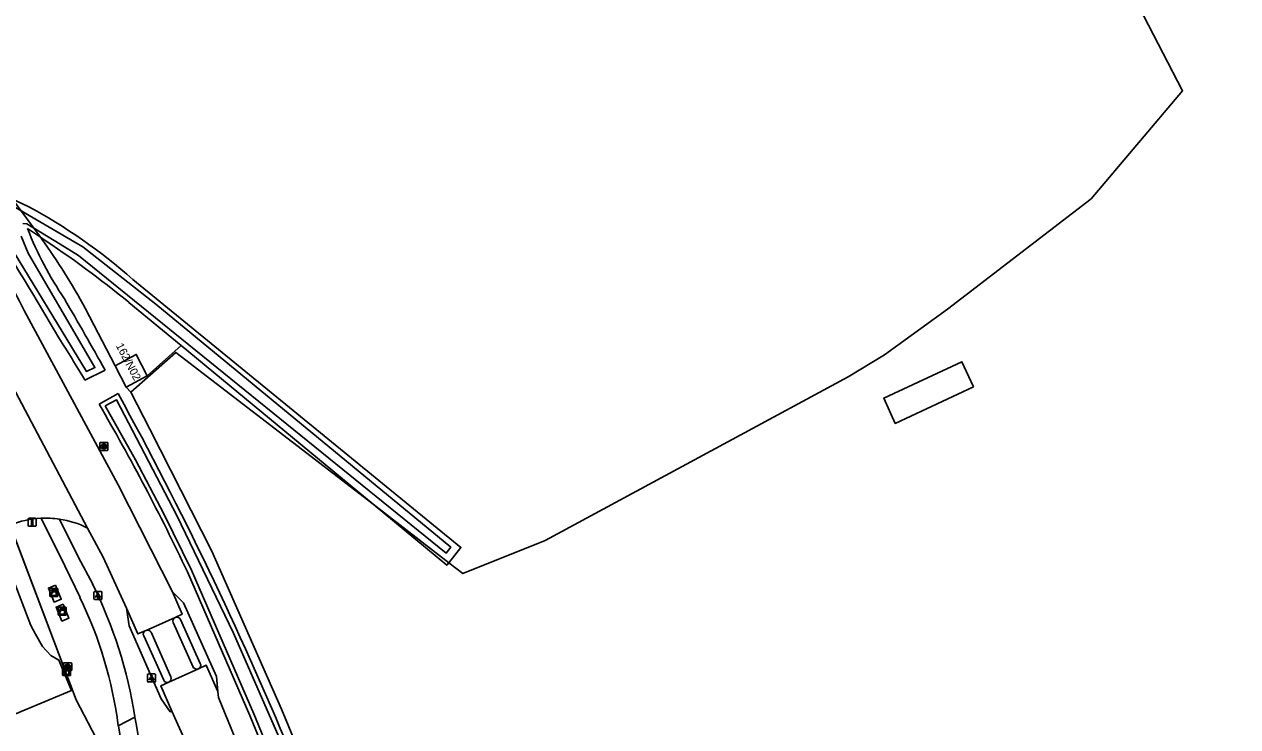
# Model space of a CAD drawing. Extents: x 156061 to 157804, y 383451 to 385640.
# Drawn here: x 157555.9 to 157707.5, y 383885.9 to 383973.7 of the extents above; entities that cross this region are included whole.
import ezdxf

# ---------------------------------------------------------------- set-up
doc = ezdxf.new("R2010")
doc.units = 0
for name, color, linetype in [('IMGEO_Bouwland', 7, 'Continuous'), ('IMGEO_Brandkraan', 7, 'Continuous'), ('IMGEO_Fietspad_gesloten', 7, 'Continuous'), ('IMGEO_Grasland_overig', 7, 'Continuous'), ('IMGEO_Groenvoorziening', 7, 'Continuous'), ('IMGEO_Hek', 7, 'Continuous'), ('IMGEO_Kast', 7, 'Continuous'), ('IMGEO_Lage_trafo', 7, 'Continuous'), ('IMGEO_Lichtpunt', 7, 'Continuous'), ('IMGEO_Muur', 7, 'Continuous'), ('IMGEO_Pand', 7, 'Continuous'), ('IMGEO_Pand_nummerreeks', 7, 'Continuous'), ('IMGEO_Rijbaan_lokaal_gesloten', 7, 'Continuous'), ('IMGEO_Rijbaan_lokaal_open', 7, 'Continuous'), ('IMGEO_Rioolput', 7, 'Continuous'), ('IMGEO_Verkeersbordpaal', 7, 'Continuous'), ('IMGEO_Voetpad_open', 7, 'Continuous'), ('IMGEO_Waterloop', 7, 'Continuous'), ('IMGEO_Woonerf_open', 7, 'Continuous')]:
    doc.layers.add(name, color=color, linetype=linetype)

msp = doc.modelspace()

# ---------------------------------------------------------------- linework, layer by layer
at = {"layer": 'IMGEO_Bouwland'}
for points in [[(157608.98, 383906.43), (157610.74, 383905.07), (157621.02, 383909.21), (157658.89, 383929.67), (157663.41, 383932.41), (157671.29, 383938.14), (157689.24, 383951.93), (157700.65, 383965.44), (157683.71, 383998.2), (157679.87, 383996.94), (157678.86, 384000), (157676.51, 384007.11)], [(157608.98, 383906.43), (157608.72, 383906.11), (157599.51, 383913.73), (157575.52, 383933.59)], [(157702.8, 383849.36), (157707.55, 383840.38), (157700.2, 383834.34), (157695.92, 383830.81), (157693.54, 383829.05), (157691.04, 383827.5), (157689.84, 383826.75), (157683.07, 383823.26), (157676.59, 383820.43), (157634.61, 383803.39), (157626.26, 383803.73), (157620.27, 383810.26), (157611.86, 383828.59), (157592.66, 383877.06), (157588.09, 383888.13), (157579.36, 383907.86), (157571.61, 383923.12), (157569.27, 383927.73), (157568.67, 383928.38)]]:
    msp.add_lwpolyline(points, dxfattribs=at)
at = {"layer": 'IMGEO_Brandkraan'}
for p, q in [((157565.39, 383920.54), (157565.39, 383921.39)), ((157565.46, 383921.46), (157566.32, 383921.46)), ((157565.9, 383920.68), (157565.87, 383920.68)), ((157565.88, 383921.24), (157565.9, 383921.24)), ((157566.39, 383921.39), (157566.39, 383920.54)), ((157566.32, 383920.46), (157565.46, 383920.46))]:
    msp.add_line(p, q, dxfattribs=at)
for points in [[(157565.39, 383920.54), (157565.39, 383921.39)], [(157565.46, 383921.46), (157566.32, 383921.46)], [(157565.74, 383921.16), (157565.74, 383920.76), (157565.95, 383920.76)], [(157565.97, 383921.16), (157565.74, 383921.16)], [(157565.92, 383921.08), (157565.86, 383921.08), (157565.86, 383921)], [(157565.86, 383921), (157565.92, 383921)], [(157565.92, 383920.93), (157565.86, 383920.93), (157565.86, 383920.85)], [(157565.86, 383920.85), (157565.92, 383920.85)], [(157566.39, 383921.39), (157566.39, 383920.54)], [(157566.32, 383920.46), (157565.46, 383920.46)]]:
    msp.add_lwpolyline(points, dxfattribs=at)
for centre, radius, start, end in [((157565.47, 383921.39), 0.0765, 91.552, 178.448), ((157565.47, 383921.39), 0.0765, 91.552, 178.448), ((157565.47, 383920.54), 0.0765, 181.552, 268.448), ((157565.47, 383920.54), 0.0765, 181.552, 268.448), ((157565.92, 383921.04), 0.0379, 267.8285, 90.9355), ((157565.92, 383920.89), 0.0404, 269.8759, 90.5077), ((157565.96, 383921.01), 0.251, 268.6676, 293.5347), ((157565.97, 383921.02), 0.145, 59.4692, 91.5367), ((157566, 383921.06), 0.0922, 285.5137, 58.1501), ((157566, 383920.87), 0.105, 301.3115, 78.989), ((157566.31, 383921.39), 0.0765, 1.552, 88.448), ((157566.31, 383921.39), 0.0765, 1.552, 88.448), ((157566.31, 383920.54), 0.0765, 271.552, 358.448), ((157566.31, 383920.54), 0.0765, 271.552, 358.448)]:
    msp.add_arc(centre, radius, start, end, dxfattribs=at)
for centre, major_axis, ratio, start_param, end_param in [((157565.88, 383920.96), (-0.387, 0.002), 0.722429, 4.712389, 7.853982), ((157565.9, 383920.96), (-0.39, 0.002), 0.717154, 1.570796, 4.712389)]:
    msp.add_ellipse(centre, major_axis=major_axis, ratio=ratio, start_param=start_param, end_param=end_param, dxfattribs=at)
at = {"layer": 'IMGEO_Fietspad_gesloten'}
for points in [[(157558.03, 383912), (157561.01, 383906.05), (157562.9, 383902.08)], [(157564.49, 383903.75), (157562.73, 383907.09), (157560.33, 383911.89)], [(157569.76, 383887.14), (157567.68, 383886.03)]]:
    msp.add_lwpolyline(points, dxfattribs=at)
for centre, radius, start, end in [((157558.61, 383900.32), 11.69, 81.5344, 92.8402), ((157512.71, 383878.19), 57.74, 8.9216, 26.283), ((157515.53, 383879.2), 52.6, 7.4631, 25.7787), ((157650.23, 383900.28), 81.53, 189.2732, 201.2187), ((157649.02, 383899.57), 82.45, 189.4495, 201.0896)]:
    msp.add_arc(centre, radius, start, end, dxfattribs=at)
at = {"layer": 'IMGEO_Grasland_overig'}
for points in [[(157558.11, 383946.93), (157557.98, 383947.12)], [(157575.52, 383933.59), (157569, 383938.98)], [(157567.3, 383931.05), (157563.55, 383938.24)], [(157575.52, 383933.59), (157571.31, 383929.81)], [(157553.25, 383886.86), (157561.82, 383890.46), (157560.26, 383894.25), (157559.24, 383894.85), (157558.2, 383895.95), (157557.34, 383897.5), (157556.74, 383898.58), (157552.12, 383910.57)], [(157554.17, 383911.13), (157562.42, 383889.31), (157565.92, 383882.59)]]:
    msp.add_lwpolyline(points, dxfattribs=at)
for centre, radius, start, end in [((157477.63, 383826.71), 144.76, 50.8627, 56.2846), ((157490.52, 383898.58), 83.1, 28.5032, 35.5798)]:
    msp.add_arc(centre, radius, start, end, dxfattribs=at)
at = {"layer": 'IMGEO_Groenvoorziening'}
for points in [[(157554.47, 383951.89), (157556.32, 383951.02)], [(157557.98, 383947.12), (157556.34, 383948.2)], [(157569.52, 383941.83), (157610.5, 383908.34), (157608.98, 383906.43)], [(157566.04, 383930.51), (157563.52, 383929.25)], [(157565.29, 383926.26), (157567.67, 383927.57)], [(157589.13, 383882.87), (157607.44, 383836.2), (157605.43, 383835.37), (157584.11, 383887.33), (157576.32, 383905.28)]]:
    msp.add_lwpolyline(points, dxfattribs=at)
for centre, radius, start, end in [((157206.53, 383728.93), 409.14, 30.1696, 34.9235), ((157524.04, 383890.59), 68.51, 48.407, 61.8863), ((157597.91, 383964.44), 44.63, 201.3477, 214.1031), ((157158.63, 383703.58), 466.34, 29.118, 30.3786), ((157329.09, 383788.72), 273.32, 30.94, 32.2461), ((157159.81, 383704.27), 464.98, 22.5876, 28.7008), ((157328.57, 383788.4), 273.93, 25.2559, 30.2157)]:
    msp.add_arc(centre, radius, start, end, dxfattribs=at)
at = {"layer": 'IMGEO_Hek'}
for points in [[(157683.71, 383998.2), (157700.65, 383965.44)], [(157608.98, 383906.43), (157610.74, 383905.07), (157621.02, 383909.21), (157658.89, 383929.67), (157663.41, 383932.41), (157671.29, 383938.14), (157689.24, 383951.93), (157700.65, 383965.44)], [(157554.47, 383951.89), (157557.98, 383947.12)], [(157557.98, 383947.12), (157558.11, 383946.93)], [(157567.3, 383931.05), (157563.55, 383938.24)], [(157569.27, 383927.73), (157574.89, 383932.72), (157599.51, 383913.73)], [(157569.27, 383927.73), (157568.67, 383928.38)], [(157599.51, 383913.73), (157608.98, 383906.43)]]:
    msp.add_lwpolyline(points, dxfattribs=at)
msp.add_arc((157490.52, 383898.58), 83.1, 28.5032, 35.5798, dxfattribs=at)
at = {"layer": 'IMGEO_Kast'}
for p, q in [((157559.14, 383902.27), (157559.14, 383903.11)), ((157559.14, 383903.11), (157559.14, 383902.27)), ((157559.22, 383903.2), (157560.06, 383903.2)), ((157560.06, 383903.2), (157559.22, 383903.2)), ((157560.14, 383903.12), (157560.14, 383902.28)), ((157560.14, 383902.28), (157560.14, 383903.12)), ((157560.07, 383902.2), (157559.23, 383902.2)), ((157559.23, 383902.2), (157560.07, 383902.2)), ((157560.17, 383899.96), (157560.17, 383900.8)), ((157560.17, 383900.8), (157560.17, 383899.96)), ((157560.24, 383900.88), (157561.08, 383900.88)), ((157561.08, 383900.88), (157560.24, 383900.88)), ((157561.17, 383900.81), (157561.17, 383899.97)), ((157561.17, 383899.97), (157561.17, 383900.81)), ((157561.09, 383899.88), (157560.25, 383899.88)), ((157560.25, 383899.88), (157561.09, 383899.88)), ((157560.71, 383892.4), (157560.71, 383893.24)), ((157560.71, 383893.24), (157560.71, 383892.4)), ((157560.79, 383893.32), (157561.63, 383893.32)), ((157561.63, 383893.32), (157560.79, 383893.32)), ((157561.71, 383893.25), (157561.71, 383892.41)), ((157561.71, 383892.41), (157561.71, 383893.25)), ((157561.64, 383892.32), (157560.8, 383892.32)), ((157560.8, 383892.32), (157561.64, 383892.32))]:
    msp.add_line(p, q, dxfattribs=at)
for points in [[(157559.34, 383902.99), (157559.94, 383902.99), (157559.94, 383902.9), (157559.34, 383902.9), (157559.34, 383902.99)], [(157559.34, 383902.81), (157559.94, 383902.81), (157559.94, 383902.33), (157559.34, 383902.33), (157559.34, 383902.81)], [(157560.36, 383900.67), (157560.96, 383900.67), (157560.96, 383900.59), (157560.36, 383900.59), (157560.36, 383900.67)], [(157560.36, 383900.5), (157560.96, 383900.5), (157560.96, 383900.01), (157560.36, 383900.01), (157560.36, 383900.5)], [(157560.91, 383893.11), (157561.51, 383893.11), (157561.51, 383893.03), (157560.91, 383893.03), (157560.91, 383893.11)], [(157560.91, 383892.94), (157561.51, 383892.94), (157561.51, 383892.45), (157560.91, 383892.45), (157560.91, 383892.94)]]:
    msp.add_lwpolyline(points, dxfattribs=at)
for centre in [(157559.42, 383902.66), (157560.45, 383900.34), (157560.99, 383892.79)]:
    msp.add_circle(centre, 0.0377, dxfattribs=at)
for centre, start, end in [((157559.22, 383903.12), 92.4484, 184.2845), ((157559.22, 383903.12), 92.4484, 184.2845), ((157560.07, 383903.12), 2.4484, 94.2845), ((157560.07, 383903.12), 2.4484, 94.2845), ((157559.22, 383902.28), 182.4484, 274.2845), ((157559.22, 383902.28), 182.4484, 274.2845), ((157560.07, 383902.28), 272.4484, 4.2845), ((157560.07, 383902.28), 272.4484, 4.2845), ((157560.25, 383900.8), 92.4484, 184.2845), ((157560.25, 383900.8), 92.4484, 184.2845), ((157561.09, 383900.8), 2.4484, 94.2845), ((157561.09, 383900.8), 2.4484, 94.2845), ((157560.25, 383899.96), 182.4484, 274.2845), ((157560.25, 383899.96), 182.4484, 274.2845), ((157561.09, 383899.96), 272.4484, 4.2845), ((157561.09, 383899.96), 272.4484, 4.2845), ((157560.79, 383893.24), 92.4484, 184.2845), ((157560.79, 383893.24), 92.4484, 184.2845), ((157561.64, 383893.24), 2.4484, 94.2845), ((157561.64, 383893.24), 2.4484, 94.2845), ((157560.79, 383892.4), 182.4484, 274.2845), ((157560.79, 383892.4), 182.4484, 274.2845), ((157561.64, 383892.4), 272.4484, 4.2845), ((157561.64, 383892.4), 272.4484, 4.2845)]:
    msp.add_arc(centre, 0.0779, start, end, dxfattribs=at)
at = {"layer": 'IMGEO_Lage_trafo'}
for points in [[(157559.83, 383903.62), (157558.95, 383903.26), (157559.67, 383901.51), (157560.55, 383901.87), (157559.83, 383903.62)], [(157560.8, 383901.25), (157559.92, 383900.89), (157560.64, 383899.14), (157561.52, 383899.5), (157560.8, 383901.25)]]:
    msp.add_lwpolyline(points, dxfattribs=at)
at = {"layer": 'IMGEO_Lichtpunt'}
for p, q in [((157564.64, 383902.73), (157564.64, 383901.93)), ((157564.64, 383902.73), (157564.64, 383901.93)), ((157565.55, 383902.83), (157564.74, 383902.83)), ((157565.55, 383902.83), (157564.74, 383902.83)), ((157565.64, 383901.93), (157565.64, 383902.73)), ((157565.64, 383901.93), (157565.64, 383902.73)), ((157564.74, 383901.83), (157565.55, 383901.83)), ((157564.74, 383901.83), (157565.55, 383901.83)), ((157571.35, 383892.42), (157571.35, 383891.61)), ((157571.35, 383892.42), (157571.35, 383891.61)), ((157572.25, 383892.52), (157571.44, 383892.52)), ((157572.25, 383892.52), (157571.44, 383892.52)), ((157572.35, 383891.61), (157572.35, 383892.42)), ((157572.35, 383891.61), (157572.35, 383892.42)), ((157571.44, 383891.52), (157572.25, 383891.52)), ((157571.44, 383891.52), (157572.25, 383891.52))]:
    msp.add_line(p, q, dxfattribs=at)
for points in [[(157565.02, 383902.4), (157565.06, 383902.37), (157564.87, 383902.11), (157564.83, 383902.14), (157565.02, 383902.4)], [(157565.12, 383902.35), (157565.17, 383902.35), (157565.17, 383902.03), (157565.12, 383902.03), (157565.12, 383902.35)], [(157565.23, 383902.37), (157565.27, 383902.4), (157565.45, 383902.13), (157565.42, 383902.11), (157565.23, 383902.37)], [(157571.72, 383892.08), (157571.76, 383892.06), (157571.57, 383891.79), (157571.54, 383891.82), (157571.72, 383892.08)], [(157571.82, 383892.04), (157571.87, 383892.04), (157571.87, 383891.71), (157571.82, 383891.71), (157571.82, 383892.04)], [(157571.93, 383892.06), (157571.97, 383892.08), (157572.16, 383891.82), (157572.12, 383891.79), (157571.93, 383892.06)]]:
    msp.add_lwpolyline(points, dxfattribs=at)
for centre in [(157565.14, 383902.53), (157571.85, 383892.22)]:
    msp.add_circle(centre, 0.0994, dxfattribs=at)
for centre, start, end in [((157564.74, 383902.73), 90, 180), ((157564.74, 383902.73), 90, 180), ((157565.55, 383902.73), 0, 90), ((157565.55, 383902.73), 0, 90), ((157564.74, 383901.93), 180, 270), ((157564.74, 383901.93), 180, 270), ((157565.55, 383901.93), 270, 0), ((157565.55, 383901.93), 270, 360), ((157571.44, 383892.42), 90, 180), ((157571.44, 383892.42), 90, 180), ((157572.25, 383892.42), 0, 90), ((157572.25, 383892.42), 0, 90), ((157571.44, 383891.61), 180, 270), ((157571.44, 383891.61), 180, 270), ((157572.25, 383891.61), 270, 0), ((157572.25, 383891.61), 270, 360)]:
    msp.add_arc(centre, 0.0946, start, end, dxfattribs=at)
at = {"layer": 'IMGEO_Muur'}
msp.add_lwpolyline([(157554.19, 383911.1), (157562.42, 383889.31)], dxfattribs=at)
at = {"layer": 'IMGEO_Pand'}
for points in [[(157567.3, 383931.05), (157569.93, 383932.48), (157571.31, 383929.81)], [(157674.54, 383928.41), (157664.75, 383923.85), (157663.32, 383927.02), (157673.08, 383931.55), (157674.54, 383928.41)], [(157568.67, 383928.38), (157567.3, 383931.05)], [(157571.31, 383929.81), (157568.67, 383928.38)]]:
    msp.add_lwpolyline(points, dxfattribs=at)
at = {"layer": 'IMGEO_Rijbaan_lokaal_gesloten'}
for points in [[(157555.94, 383937.98), (157567.65, 383916.15), (157574.44, 383902.8)], [(157552.88, 383931.4), (157563.85, 383910.77)], [(157563.85, 383910.77), (157565.81, 383907.11), (157568.7, 383900.75)], [(157574.78, 383899.59), (157575.65, 383899.99), (157574.44, 383902.8)], [(157568.7, 383900.75), (157570.14, 383897.53), (157571.05, 383897.92)], [(157571.05, 383897.92), (157571.17, 383897.97)], [(157580.13, 383890.35), (157578.67, 383893.61), (157577.71, 383893.16)], [(157573.99, 383891.5), (157573, 383891.06), (157574.36, 383887.86)], [(157612.75, 383810.25), (157610.74, 383815.24), (157601.93, 383836.64), (157594.17, 383855.64), (157583.74, 383880.91), (157580.2, 383889.6), (157580.13, 383890.35)], [(157574.36, 383887.86), (157578.42, 383878.92), (157590.68, 383848.25), (157595.7, 383836.04)]]:
    msp.add_lwpolyline(points, dxfattribs=at)
msp.add_arc((157379.41, 383843.74), 200.11, 28.0956, 40.0394, dxfattribs=at)
at = {"layer": 'IMGEO_Rijbaan_lokaal_open'}
for points in [[(157571.17, 383897.97), (157574.78, 383899.59)], [(157574.54, 383898.95), (157577.02, 383893.38)], [(157574.26, 383892.17), (157571.79, 383897.73)], [(157577.71, 383893.16), (157573.99, 383891.5)]]:
    msp.add_lwpolyline(points, dxfattribs=at)
for centre, radius, start, end in [((157575.02, 383899.14), 0.514, 118.0121, 201.0728), ((157571.34, 383897.49), 0.511, 28.1021, 109.7612), ((157577.49, 383893.68), 0.56, 212.0108, 292.8668), ((157573.76, 383891.98), 0.532, 295.3711, 20.9378)]:
    msp.add_arc(centre, radius, start, end, dxfattribs=at)
at = {"layer": 'IMGEO_Rioolput'}
for p, q in [((157560.85, 383893), (157560.85, 383893.85)), ((157560.93, 383893.93), (157561.78, 383893.93)), ((157561.34, 383893.7), (157561.37, 383893.7)), ((157561.86, 383893.85), (157561.86, 383893)), ((157561.78, 383892.92), (157560.93, 383892.92)), ((157561.36, 383893.15), (157561.34, 383893.15))]:
    msp.add_line(p, q, dxfattribs=at)
for points in [[(157560.85, 383893), (157560.85, 383893.85)], [(157560.93, 383893.93), (157561.78, 383893.93)], [(157561.44, 383893.62), (157561.19, 383893.62), (157561.19, 383893.22)], [(157561.19, 383893.22), (157561.32, 383893.22), (157561.32, 383893.39), (157561.33, 383893.39)], [(157561.37, 383893.54), (157561.32, 383893.54), (157561.32, 383893.46)], [(157561.32, 383893.46), (157561.37, 383893.46)], [(157561.37, 383893.36), (157561.44, 383893.22), (157561.58, 383893.22), (157561.52, 383893.35)], [(157561.86, 383893.85), (157561.86, 383893)], [(157561.78, 383892.92), (157560.93, 383892.92)]]:
    msp.add_lwpolyline(points, dxfattribs=at)
for centre, radius, start, end in [((157560.93, 383893.85), 0.0765, 91.552, 178.448), ((157560.93, 383893.85), 0.0765, 91.552, 178.448), ((157561.32, 383893.33), 0.0533, 26.0293, 88.6989), ((157561.37, 383893.45), 0.0964, 77.0061, 93.1865), ((157561.35, 383893.65), 0.19, 274.7715, 282.9687), ((157561.39, 383893.5), 0.0378, 276.6634, 79.6772), ((157561.44, 383893.51), 0.109, 350.3612, 89.416), ((157561.44, 383893.51), 0.112, 277.5842, 350.9817), ((157561.42, 383893.3), 0.108, 29.5134, 73.7905), ((157561.78, 383893.85), 0.0765, 1.552, 88.448), ((157561.78, 383893.85), 0.0765, 1.552, 88.448), ((157560.93, 383893), 0.0765, 181.552, 268.448), ((157560.93, 383893), 0.0765, 181.552, 268.448), ((157561.78, 383893), 0.0765, 271.552, 358.448), ((157561.78, 383893), 0.0765, 271.552, 358.448)]:
    msp.add_arc(centre, radius, start, end, dxfattribs=at)
for centre, major_axis, ratio, start_param, end_param in [((157561.34, 383893.42), (-0.387, 0.002), 0.722429, 4.712389, 7.853982), ((157561.37, 383893.42), (-0.39, 0.002), 0.717154, 1.570796, 4.712389)]:
    msp.add_ellipse(centre, major_axis=major_axis, ratio=ratio, start_param=start_param, end_param=end_param, dxfattribs=at)
at = {"layer": 'IMGEO_Verkeersbordpaal'}
for p, q in [((157556.42, 383911.08), (157556.42, 383911.88)), ((157556.42, 383911.88), (157556.42, 383911.08)), ((157556.52, 383911.98), (157557.31, 383911.98)), ((157557.31, 383911.98), (157556.52, 383911.98)), ((157557.41, 383911.88), (157557.41, 383911.08)), ((157557.41, 383911.08), (157557.41, 383911.88)), ((157557.31, 383910.98), (157556.52, 383910.98)), ((157556.52, 383910.98), (157557.31, 383910.98))]:
    msp.add_line(p, q, dxfattribs=at)
msp.add_lwpolyline([(157556.84, 383911.85), (157556.99, 383911.85), (157556.99, 383911.1), (157556.84, 383911.1), (157556.84, 383911.85)], dxfattribs=at)
for centre, start, end in [((157556.52, 383911.88), 90, 180), ((157556.52, 383911.88), 90, 180), ((157557.31, 383911.88), 0, 90), ((157557.31, 383911.88), 360, 90), ((157556.52, 383911.08), 180, 270), ((157556.52, 383911.08), 180, 270), ((157557.31, 383911.08), 270, 0), ((157557.31, 383911.08), 270, 0)]:
    msp.add_arc(centre, 0.1, start, end, dxfattribs=at)
at = {"layer": 'IMGEO_Voetpad_open'}
for points in [[(157574.44, 383902.8), (157575.84, 383901.42), (157579.95, 383892.19), (157580.13, 383890.35)], [(157568.7, 383900.75), (157569.03, 383898.55), (157573.06, 383889.42), (157574.18, 383887.79), (157574.36, 383887.86)], [(157577.93, 383893.84), (157575.47, 383899.34)], [(157570.86, 383897.3), (157573.36, 383891.74)]]:
    msp.add_lwpolyline(points, dxfattribs=at)
for centre, radius, start, end in [((157575, 383899.11), 0.522, 25.3694, 114.2893), ((157571.25, 383897.52), 0.445, 116.49, 209.4482), ((157577.47, 383893.62), 0.511, 297.5361, 26.0008), ((157573.81, 383891.99), 0.521, 208.7614, 289.5901)]:
    msp.add_arc(centre, radius, start, end, dxfattribs=at)
at = {"layer": 'IMGEO_Waterloop'}
for points in [[(157553.33, 383951.7), (157563.27, 383945.93), (157572.36, 383938.75), (157609.22, 383908.39), (157608.66, 383907.63), (157562.7, 383944.84), (157560.43, 383946.26), (157556.27, 383948.79), (157555.76, 383948.82)], [(157555.54, 383947.24), (157556.41, 383945.12), (157564.76, 383930.83), (157563.7, 383930.34), (157553.42, 383947.27)], [(157566.06, 383926.04), (157567.44, 383926.81), (157575.01, 383912.34), (157582.07, 383897.62), (157588.61, 383882.66), (157606.71, 383836.51), (157605.73, 383836.1), (157584.63, 383887.55), (157576.83, 383905.51), (157573.43, 383912.45), (157569.84, 383919.3), (157566.06, 383926.04)]]:
    msp.add_lwpolyline(points, dxfattribs=at)
at = {"layer": 'IMGEO_Woonerf_open'}
for centre, radius, start, end in [((157558.61, 383900.36), 11.65, 92.8801, 112.3915), ((157558.6, 383900.34), 11.67, 63.2757, 81.4738)]:
    msp.add_arc(centre, radius, start, end, dxfattribs=at)

# ---------------------------------------------------------------- texts
at = {"layer": 'IMGEO_Pand_nummerreeks'}
msp.add_text('162/N02', height=1, rotation=297.699, dxfattribs=at).set_placement((157567.34, 383933.57))

doc.saveas('drawing.dxf')
